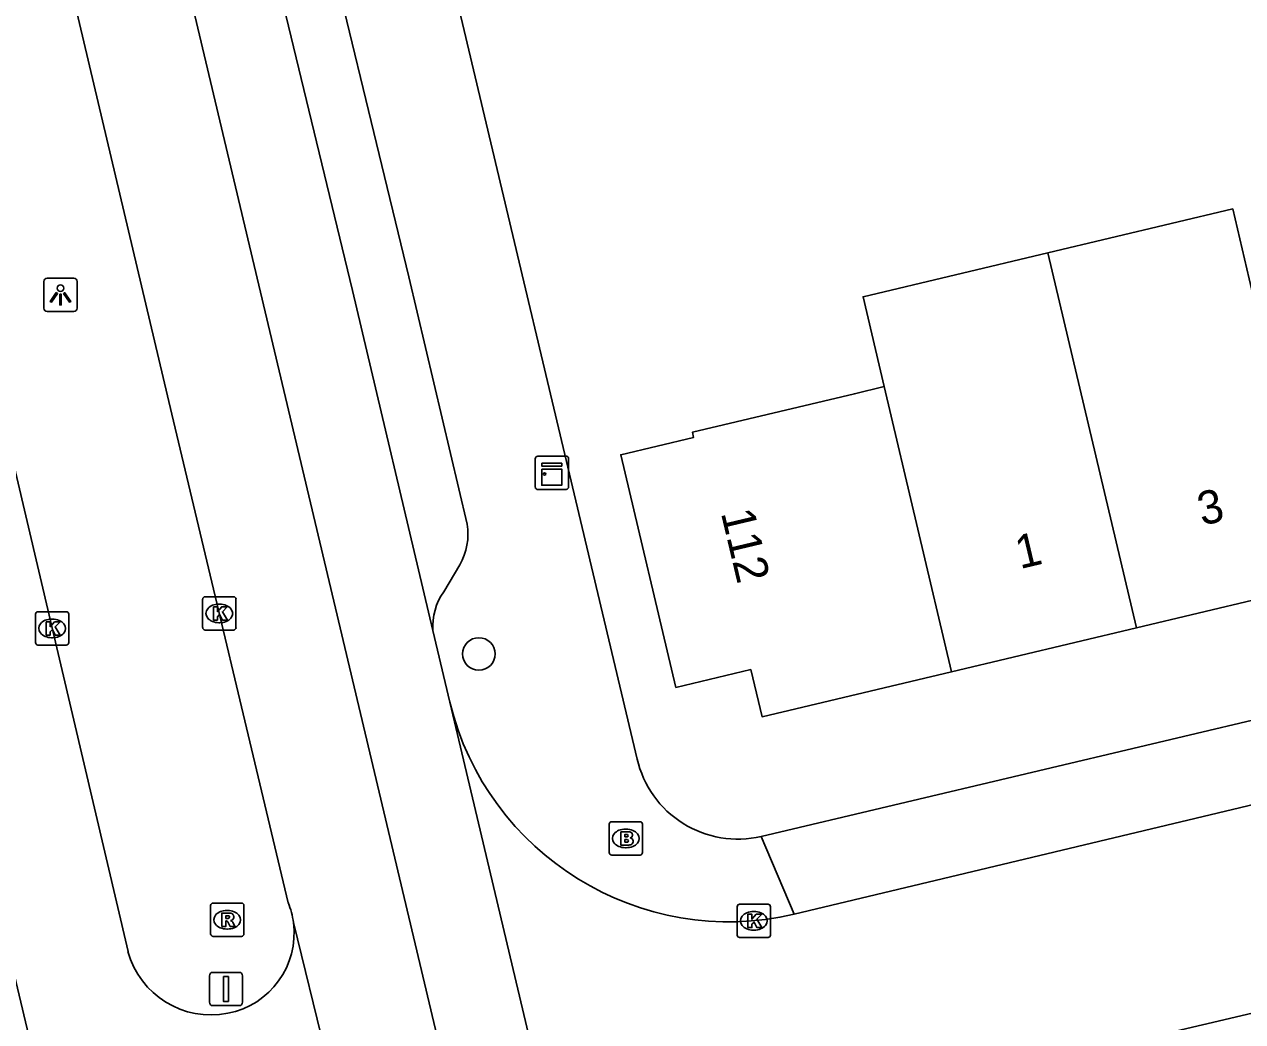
# Model space of a CAD drawing. Extents: x 158474 to 159560, y 388525 to 389605.
# Drawn here: x 159285.1 to 159321.68, y 388760.51 to 388790.44 of the extents above; entities that cross this region are included whole.
import ezdxf

# ---------------------------------------------------------------- set-up
doc = ezdxf.new("R2010")
doc.units = 0
for name, color, linetype in [('IMGEO_Boom', 7, 'Continuous'), ('IMGEO_Brandkraan', 7, 'Continuous'), ('IMGEO_Kast', 7, 'Continuous'), ('IMGEO_Kolk', 7, 'Continuous'), ('IMGEO_Lichtpunt', 7, 'Continuous'), ('IMGEO_Pand', 7, 'Continuous'), ('IMGEO_Pand_nummerreeks', 7, 'Continuous'), ('IMGEO_Rijbaan_lokaal_gesloten', 7, 'Continuous'), ('IMGEO_Rijbaan_lokaal_open', 7, 'Continuous'), ('IMGEO_Rioolput', 7, 'Continuous'), ('IMGEO_Verkeersbordpaal', 7, 'Continuous'), ('IMGEO_Voetpad_open', 7, 'Continuous')]:
    doc.layers.add(name, color=color, linetype=linetype)

msp = doc.modelspace()

# ---------------------------------------------------------------- linework, layer by layer
at = {"layer": 'IMGEO_Boom'}
msp.add_circle((159298.743, 388771.546), 0.489, dxfattribs=at)
at = {"layer": 'IMGEO_Brandkraan'}
for p, q in [((159302.657, 388765.585), (159302.657, 388766.437)), ((159302.732, 388766.511), (159303.584, 388766.511)), ((159303.145, 388766.291), (159303.17, 388766.291)), ((159303.658, 388766.437), (159303.658, 388765.585)), ((159303.584, 388765.511), (159302.732, 388765.511)), ((159303.168, 388765.731), (159303.143, 388765.731))]:
    msp.add_line(p, q, dxfattribs=at)
for points in [[(159302.657, 388765.585), (159302.657, 388766.437)], [(159302.732, 388766.511), (159303.584, 388766.511)], [(159303.005, 388766.211), (159303.005, 388765.811), (159303.218, 388765.811)], [(159303.236, 388766.211), (159303.005, 388766.211)], [(159303.658, 388766.437), (159303.658, 388765.585)], [(159303.184, 388766.13), (159303.13, 388766.13), (159303.13, 388766.054)], [(159303.13, 388766.054), (159303.183, 388766.054)], [(159303.192, 388765.978), (159303.13, 388765.978), (159303.13, 388765.897)], [(159303.13, 388765.897), (159303.192, 388765.897)], [(159303.584, 388765.511), (159302.732, 388765.511)]]:
    msp.add_lwpolyline(points, dxfattribs=at)
for centre, radius, start, end in [((159302.734, 388766.435), 0.0765, 91.552, 178.448), ((159302.734, 388766.435), 0.0765, 91.552, 178.448), ((159303.24, 388766.066), 0.145, 59.4692, 91.5367), ((159303.265, 388766.113), 0.0922, 285.5137, 58.1501), ((159303.582, 388766.435), 0.0765, 1.552, 88.448), ((159303.582, 388766.435), 0.0765, 1.552, 88.448), ((159303.185, 388766.092), 0.0379, 267.8285, 90.9355), ((159303.193, 388765.937), 0.0404, 269.8759, 90.5077), ((159303.224, 388766.062), 0.251, 268.6676, 293.5347), ((159303.27, 388765.921), 0.105, 301.3115, 78.989), ((159302.734, 388765.587), 0.0765, 181.552, 268.448), ((159302.734, 388765.587), 0.0765, 181.552, 268.448), ((159303.582, 388765.587), 0.0765, 271.552, 358.448), ((159303.582, 388765.587), 0.0765, 271.552, 358.448)]:
    msp.add_arc(centre, radius, start, end, dxfattribs=at)
for centre, major_axis, ratio, start_param, end_param in [((159303.144, 388766.011), (-0.387, 0.002), 0.722429, 4.712389, 7.853982), ((159303.169, 388766.011), (-0.39, 0.002), 0.717154, 1.570796, 4.712389)]:
    msp.add_ellipse(centre, major_axis=major_axis, ratio=ratio, start_param=start_param, end_param=end_param, dxfattribs=at)
at = {"layer": 'IMGEO_Kast'}
for p, q in [((159300.439, 388776.558), (159300.439, 388777.399)), ((159300.439, 388777.399), (159300.439, 388776.558)), ((159300.514, 388777.483), (159301.355, 388777.483)), ((159301.355, 388777.483), (159300.514, 388777.483)), ((159301.439, 388777.408), (159301.439, 388776.567)), ((159301.439, 388776.567), (159301.439, 388777.408)), ((159301.364, 388776.483), (159300.523, 388776.483)), ((159300.523, 388776.483), (159301.364, 388776.483))]:
    msp.add_line(p, q, dxfattribs=at)
for points in [[(159300.634, 388777.273), (159301.234, 388777.273), (159301.234, 388777.188), (159300.634, 388777.188), (159300.634, 388777.273)], [(159300.634, 388777.098), (159301.234, 388777.098), (159301.234, 388776.609), (159300.634, 388776.609), (159300.634, 388777.098)]]:
    msp.add_lwpolyline(points, dxfattribs=at)
msp.add_circle((159300.718, 388776.947), 0.0377, dxfattribs=at)
for centre, start, end in [((159300.517, 388777.405), 92.4484, 184.2845), ((159300.517, 388777.405), 92.4484, 184.2845), ((159301.361, 388777.405), 2.4484, 94.2845), ((159301.361, 388777.405), 2.4484, 94.2845), ((159300.517, 388776.561), 182.4484, 274.2845), ((159300.517, 388776.561), 182.4484, 274.2845), ((159301.361, 388776.561), 272.4484, 4.2845), ((159301.361, 388776.561), 272.4484, 4.2845)]:
    msp.add_arc(centre, 0.0779, start, end, dxfattribs=at)
at = {"layer": 'IMGEO_Kolk'}
for p, q in [((159290.449, 388772.338), (159290.449, 388773.19)), ((159290.524, 388773.264), (159291.376, 388773.264)), ((159291.45, 388773.19), (159291.45, 388772.338)), ((159285.503, 388772.814), (159286.355, 388772.814)), ((159290.937, 388773.044), (159290.962, 388773.044)), ((159285.428, 388771.888), (159285.428, 388772.74)), ((159285.916, 388772.594), (159285.941, 388772.594)), ((159286.429, 388772.74), (159286.429, 388771.888)), ((159290.96, 388772.484), (159290.935, 388772.484)), ((159285.939, 388772.034), (159285.914, 388772.034)), ((159291.376, 388772.264), (159290.524, 388772.264)), ((159286.355, 388771.814), (159285.503, 388771.814)), ((159306.575, 388764.036), (159307.427, 388764.036)), ((159306.5, 388763.11), (159306.5, 388763.962)), ((159306.988, 388763.816), (159307.013, 388763.816)), ((159307.501, 388763.962), (159307.501, 388763.11)), ((159307.011, 388763.256), (159306.986, 388763.256)), ((159307.427, 388763.036), (159306.575, 388763.036))]:
    msp.add_line(p, q, dxfattribs=at)
for points in [[(159290.449, 388772.338), (159290.449, 388773.19)], [(159290.524, 388773.264), (159291.376, 388773.264)], [(159291.45, 388773.19), (159291.45, 388772.338)], [(159285.503, 388772.814), (159286.355, 388772.814)], [(159290.77, 388772.964), (159290.893, 388772.964), (159290.893, 388772.813), (159291.023, 388772.964), (159291.187, 388772.964), (159291.041, 388772.813), (159291.194, 388772.564), (159291.042, 388772.564), (159290.957, 388772.728), (159290.893, 388772.661), (159290.893, 388772.564), (159290.77, 388772.564), (159290.77, 388772.964)], [(159285.428, 388771.888), (159285.428, 388772.74)], [(159285.749, 388772.514), (159285.872, 388772.514), (159285.872, 388772.363), (159286.002, 388772.514), (159286.166, 388772.514), (159286.02, 388772.363), (159286.173, 388772.114), (159286.021, 388772.114), (159285.936, 388772.278), (159285.872, 388772.211), (159285.872, 388772.114), (159285.749, 388772.114), (159285.749, 388772.514)], [(159286.429, 388772.74), (159286.429, 388771.888)], [(159291.376, 388772.264), (159290.524, 388772.264)], [(159286.355, 388771.814), (159285.503, 388771.814)], [(159306.575, 388764.036), (159307.427, 388764.036)], [(159306.5, 388763.11), (159306.5, 388763.962)], [(159306.821, 388763.736), (159306.944, 388763.736), (159306.944, 388763.585), (159307.074, 388763.736), (159307.238, 388763.736), (159307.092, 388763.585), (159307.245, 388763.336), (159307.093, 388763.336), (159307.008, 388763.5), (159306.944, 388763.433), (159306.944, 388763.336), (159306.821, 388763.336), (159306.821, 388763.736)], [(159307.501, 388763.962), (159307.501, 388763.11)], [(159307.427, 388763.036), (159306.575, 388763.036)]]:
    msp.add_lwpolyline(points, dxfattribs=at)
for centre, start, end in [((159290.526, 388773.188), 91.552, 178.448), ((159290.526, 388773.188), 91.552, 178.448), ((159291.374, 388773.188), 1.552, 88.448), ((159291.374, 388773.188), 1.552, 88.448), ((159285.505, 388772.738), 91.552, 178.448), ((159285.505, 388772.738), 91.552, 178.448), ((159286.353, 388772.738), 1.552, 88.448), ((159286.353, 388772.738), 1.552, 88.448), ((159290.526, 388772.34), 181.552, 268.448), ((159290.526, 388772.34), 181.552, 268.448), ((159291.374, 388772.34), 271.552, 358.448), ((159291.374, 388772.34), 271.552, 358.448), ((159285.505, 388771.89), 181.552, 268.448), ((159285.505, 388771.89), 181.552, 268.448), ((159286.353, 388771.89), 271.552, 358.448), ((159286.353, 388771.89), 271.552, 358.448), ((159306.577, 388763.96), 91.552, 178.448), ((159306.577, 388763.96), 91.552, 178.448), ((159307.425, 388763.96), 1.552, 88.448), ((159307.425, 388763.96), 1.552, 88.448), ((159306.577, 388763.112), 181.552, 268.448), ((159306.577, 388763.112), 181.552, 268.448), ((159307.425, 388763.112), 271.552, 358.448), ((159307.425, 388763.112), 271.552, 358.448)]:
    msp.add_arc(centre, 0.0765, start, end, dxfattribs=at)
for centre, major_axis, ratio, start_param, end_param in [((159290.936, 388772.764), (-0.387, 0.002), 0.722429, 4.712389, 7.853982), ((159290.961, 388772.764), (-0.39, 0.002), 0.717154, 1.570796, 4.712389), ((159285.915, 388772.314), (-0.387, 0.002), 0.722429, 4.712389, 7.853982), ((159285.94, 388772.314), (-0.39, 0.002), 0.717154, 1.570796, 4.712389), ((159306.987, 388763.536), (-0.387, 0.002), 0.722429, 4.712389, 7.853982), ((159307.012, 388763.536), (-0.39, 0.002), 0.717154, 1.570796, 4.712389)]:
    msp.add_ellipse(centre, major_axis=major_axis, ratio=ratio, start_param=start_param, end_param=end_param, dxfattribs=at)
at = {"layer": 'IMGEO_Lichtpunt'}
for p, q in [((159285.681, 388782.728), (159285.681, 388781.921)), ((159285.681, 388782.728), (159285.681, 388781.921)), ((159286.583, 388782.823), (159285.775, 388782.823)), ((159286.583, 388782.823), (159285.775, 388782.823)), ((159286.677, 388781.921), (159286.677, 388782.728)), ((159286.677, 388781.921), (159286.677, 388782.728)), ((159285.775, 388781.827), (159286.583, 388781.827)), ((159285.775, 388781.827), (159286.583, 388781.827))]:
    msp.add_line(p, q, dxfattribs=at)
for points in [[(159286.055, 388782.392), (159286.094, 388782.364), (159285.906, 388782.102), (159285.868, 388782.129), (159286.055, 388782.392)], [(159286.157, 388782.344), (159286.204, 388782.344), (159286.204, 388782.022), (159286.157, 388782.022), (159286.157, 388782.344)], [(159286.267, 388782.364), (159286.305, 388782.391), (159286.492, 388782.129), (159286.453, 388782.101), (159286.267, 388782.364)]]:
    msp.add_lwpolyline(points, dxfattribs=at)
msp.add_circle((159286.18, 388782.526), 0.0994, dxfattribs=at)
for centre, start, end in [((159285.775, 388782.728), 90, 180), ((159285.775, 388782.728), 90, 180), ((159286.583, 388782.728), 0, 90), ((159286.583, 388782.728), 0, 90), ((159285.775, 388781.921), 180, 270), ((159285.775, 388781.921), 180, 270), ((159286.583, 388781.921), 270, 0), ((159286.583, 388781.921), 270, 360)]:
    msp.add_arc(centre, 0.0946, start, end, dxfattribs=at)
at = {"layer": 'IMGEO_Pand'}
for points in [[(159315.834, 388783.585), (159321.383, 388784.903), (159322.02, 388782.207)], [(159310.919, 388779.57), (159310.282, 388782.266), (159315.834, 388783.585)], [(159318.492, 388772.332), (159315.834, 388783.585)], [(159312.941, 388771.013), (159307.247, 388769.661), (159306.91, 388771.078), (159304.661, 388770.544), (159303.003, 388777.526), (159305.192, 388778.046), (159305.155, 388778.201), (159310.02, 388779.357), (159310.919, 388779.57)], [(159310.919, 388779.57), (159312.941, 388771.013)], [(159324.043, 388773.65), (159318.492, 388772.332)], [(159318.492, 388772.332), (159312.941, 388771.013)]]:
    msp.add_lwpolyline(points, dxfattribs=at)
at = {"layer": 'IMGEO_Rijbaan_lokaal_gesloten'}
for points in [[(159318.834, 388670.194), (159286.319, 388807.116), (159279.715, 388835.25)], [(159276.343, 388834.412), (159277.901, 388827.843), (159284.536, 388799.838), (159289.528, 388778.742), (159293.018, 388764.082)], [(159271.51, 388833.21), (159279.673, 388798.682), (159283.502, 388782.632), (159288.208, 388762.614)], [(159299.905, 388687.548), (159301.738, 388687.977), (159302.196, 388688.085), (159299.002, 388702.154), (159292.436, 388729.776), (159285.132, 388760.501), (159274.982, 388803.196), (159268.084, 388832.358)], [(159297.363, 388772.254), (159294.947, 388782.456), (159291.104, 388798.335)], [(159297.873, 388770.099), (159297.363, 388772.254)], [(159297.873, 388770.099), (159302.634, 388750), (159303.106, 388748.007)], [(159293.175, 388763.484), (159296.032, 388751.838)]]:
    msp.add_lwpolyline(points, dxfattribs=at)
for centre, radius, start, end in [((159290.81, 388763.183), 2.384, 7.259, 22.1621), ((159290.752, 388763.165), 2.444, 280.6993, 7.4994), ((159290.697, 388763.294), 2.581, 195.2782, 281.3662)]:
    msp.add_arc(centre, radius, start, end, dxfattribs=at)
at = {"layer": 'IMGEO_Rijbaan_lokaal_open'}
for points in [[(159308.215, 388763.733), (159331.44, 388769.279)], [(159309.692, 388757.886), (159321.969, 388760.768), (159335.523, 388764.032)]]:
    msp.add_lwpolyline(points, dxfattribs=at)
msp.add_arc((159306.259, 388772.14), 8.631, 193.6754, 283.096, dxfattribs=at)
at = {"layer": 'IMGEO_Rioolput'}
for p, q in [((159290.687, 388763.144), (159290.687, 388763.996)), ((159290.762, 388764.07), (159291.614, 388764.07)), ((159291.688, 388763.996), (159291.688, 388763.144)), ((159291.175, 388763.85), (159291.2, 388763.85)), ((159291.198, 388763.29), (159291.173, 388763.29)), ((159291.614, 388763.07), (159290.762, 388763.07))]:
    msp.add_line(p, q, dxfattribs=at)
for points in [[(159290.687, 388763.144), (159290.687, 388763.996)], [(159290.762, 388764.07), (159291.614, 388764.07)], [(159291.688, 388763.996), (159291.688, 388763.144)], [(159291.276, 388763.768), (159291.024, 388763.77), (159291.024, 388763.37)], [(159291.202, 388763.689), (159291.148, 388763.689), (159291.148, 388763.608)], [(159291.148, 388763.608), (159291.2, 388763.608)], [(159291.024, 388763.37), (159291.148, 388763.37), (159291.148, 388763.532), (159291.159, 388763.532)], [(159291.206, 388763.503), (159291.277, 388763.37), (159291.417, 388763.37), (159291.352, 388763.496)], [(159291.614, 388763.07), (159290.762, 388763.07)]]:
    msp.add_lwpolyline(points, dxfattribs=at)
for centre, radius, start, end in [((159290.764, 388763.994), 0.0765, 91.552, 178.448), ((159290.764, 388763.994), 0.0765, 91.552, 178.448), ((159291.612, 388763.994), 0.0765, 1.552, 88.448), ((159291.612, 388763.994), 0.0765, 1.552, 88.448), ((159291.184, 388763.797), 0.19, 274.7715, 282.9687), ((159291.208, 388763.593), 0.0964, 77.0061, 93.1865), ((159291.222, 388763.65), 0.0378, 276.6634, 79.6772), ((159291.275, 388763.658), 0.109, 350.3612, 89.416), ((159291.273, 388763.658), 0.112, 277.5842, 350.9817), ((159291.158, 388763.479), 0.0533, 26.0293, 88.6989), ((159291.257, 388763.443), 0.108, 29.5134, 73.7905), ((159290.764, 388763.146), 0.0765, 181.552, 268.448), ((159290.764, 388763.146), 0.0765, 181.552, 268.448), ((159291.612, 388763.146), 0.0765, 271.552, 358.448), ((159291.612, 388763.146), 0.0765, 271.552, 358.448)]:
    msp.add_arc(centre, radius, start, end, dxfattribs=at)
for centre, major_axis, ratio, start_param, end_param in [((159291.174, 388763.57), (-0.387, 0.002), 0.722429, 4.712389, 7.853982), ((159291.199, 388763.57), (-0.39, 0.002), 0.717154, 1.570796, 4.712389)]:
    msp.add_ellipse(centre, major_axis=major_axis, ratio=ratio, start_param=start_param, end_param=end_param, dxfattribs=at)
at = {"layer": 'IMGEO_Verkeersbordpaal'}
for p, q in [((159290.655, 388761.091), (159290.655, 388761.891)), ((159290.655, 388761.891), (159290.655, 388761.091)), ((159290.755, 388761.991), (159291.545, 388761.991)), ((159291.545, 388761.991), (159290.755, 388761.991)), ((159291.645, 388761.891), (159291.645, 388761.091)), ((159291.645, 388761.091), (159291.645, 388761.891)), ((159291.545, 388760.991), (159290.755, 388760.991)), ((159290.755, 388760.991), (159291.545, 388760.991))]:
    msp.add_line(p, q, dxfattribs=at)
msp.add_lwpolyline([(159291.075, 388761.866), (159291.225, 388761.866), (159291.225, 388761.116), (159291.075, 388761.116), (159291.075, 388761.866)], dxfattribs=at)
for centre, start, end in [((159290.755, 388761.891), 90, 180), ((159290.755, 388761.891), 90, 180), ((159291.545, 388761.891), 0, 90), ((159291.545, 388761.891), 360, 90), ((159290.755, 388761.091), 180, 270), ((159290.755, 388761.091), 180, 270), ((159291.545, 388761.091), 270, 0), ((159291.545, 388761.091), 270, 0)]:
    msp.add_arc(centre, 0.1, start, end, dxfattribs=at)
at = {"layer": 'IMGEO_Voetpad_open'}
for points in [[(159291.028, 388820.9), (159303.497, 388768.394)], [(159381.001, 388796.659), (159369, 388777.58), (159342.733, 388771.26), (159339.013, 388773.592), (159307.222, 388766.073)], [(159293.569, 388795.538), (159296.637, 388782.861), (159298.393, 388775.443)], [(159298.173, 388774.222), (159297.689, 388773.415)], [(159307.222, 388766.073), (159308.215, 388763.733)]]:
    msp.add_lwpolyline(points, dxfattribs=at)
for centre, radius, start, end in [((159296.542, 388775.146), 1.874, 330.4583, 9.1137), ((159299.213, 388772.361), 1.853, 145.3298, 183.3015), ((159306.515, 388769.088), 3.097, 192.9543, 283.1927)]:
    msp.add_arc(centre, radius, start, end, dxfattribs=at)

# ---------------------------------------------------------------- texts
at = {"layer": 'IMGEO_Pand_nummerreeks'}
for s, rotation, p in [('3', 13.3609, (159320.461, 388775.39)), ('112', 283.3585, (159306.008, 388775.784)), ('1', 13.3609, (159314.992, 388774.091))]:
    msp.add_text(s, height=1, rotation=rotation, dxfattribs=at).set_placement(p)

doc.saveas('drawing.dxf')
